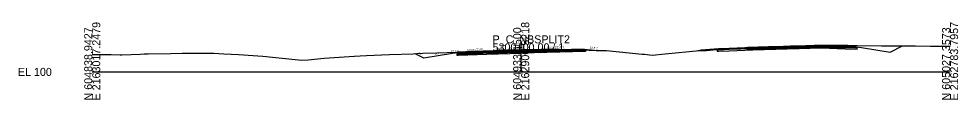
# Model space of a CAD drawing. Extents: x -26 to 1303, y -10 to 12038.
# Drawn here: x -25.7 to 302.8, y 10490.3 to 10517.3 of the extents above; entities that cross this region are included whole.
import ezdxf

# ---------------------------------------------------------------- set-up
doc = ezdxf.new("R2010")
doc.units = 0
for name, color, linetype in [('RD_GPK_XS_Cell', 7, 'Continuous'), ('RD_XS_Base', 7, 'Continuous'), ('RD_XS_ExGround', 7, 'Continuous'), ('RD_XS_ExPaveRet', 7, 'Continuous'), ('RD_XS_Greenside', 7, 'Continuous'), ('RD_XS_Pave', 7, 'Continuous'), ('RD_XS_PaveOvlay_CP', 7, 'Continuous'), ('RD_XS_TieSlope', 7, 'Continuous'), ('RD_XS_TX_Elev_EX', 7, 'Continuous'), ('RD_XS_TX_Elev_PR', 7, 'Continuous'), ('RD_XS_TX_ShdSlope', 7, 'Continuous'), ('RD_XS_TX_Slope', 7, 'Continuous')]:
    doc.layers.add(name, color=color, linetype=linetype)

msp = doc.modelspace()

# ---------------------------------------------------------------- linework, layer by layer
at = {"layer": 'RD_GPK_XS_Cell'}
for p, q in [((150, 10500), (150, 10510)), ((0, 10500), (150, 10500)), ((150, 10500), (300, 10500))]:
    msp.add_line(p, q, dxfattribs=at)
at = {"layer": 'RD_XS_Base'}
for p, q in [((138, 10506.72), (128, 10506.32)), ((150, 10507.04), (138, 10506.72)), ((138, 10506.72), (138, 10506.72)), ((138, 10506.22), (150, 10506.54)), ((150, 10507.04), (172.5, 10507.62)), ((150, 10506.54), (150, 10507.2)), ((150, 10507.2), (150, 10507.2)), ((150, 10507.2), (150, 10507.2)), ((150, 10507.2), (150, 10507.04)), ((172.5, 10507.12), (150, 10506.54)), ((150, 10507.04), (150, 10507.04)), ((150, 10506.54), (150, 10507.04)), ((150, 10507.04), (150, 10507.04)), ((150, 10507.04), (150, 10507.04)), ((150, 10506.54), (150, 10506.54)), ((172, 10507.61), (172, 10507.61)), ((172, 10507.61), (172, 10507.61)), ((172, 10507.61), (172, 10507.61)), ((172, 10507.11), (172, 10507.11)), ((172, 10507.11), (172, 10507.11)), ((172.5, 10507.62), (172.5, 10507.12)), ((172.5, 10507.59), (172.5, 10507.59)), ((218.68, 10507.74), (218.49, 10507.74)), ((218.49, 10507.74), (218.49, 10507.42)), ((218.49, 10507.42), (218.49, 10507.24)), ((218.49, 10507.24), (218.68, 10507.24)), ((218.99, 10507.76), (218.68, 10507.74)), ((218.68, 10507.24), (218.99, 10507.26)), ((222.72, 10507.91), (218.99, 10507.76)), ((218.99, 10507.26), (222.72, 10507.41)), ((231, 10508.24), (222.72, 10507.91)), ((222.72, 10507.41), (231, 10507.74)), ((243, 10508.57), (231, 10508.24)), ((231, 10507.74), (243, 10508.07)), ((243, 10508.63), (243, 10508.73)), ((243, 10508.73), (243, 10508.31)), ((247.18, 10508.69), (243, 10508.57)), ((243, 10508.57), (243, 10508.63)), ((243, 10508.57), (243, 10508.57)), ((243, 10508.57), (243, 10508.57)), ((243, 10508.25), (243, 10508.57)), ((243, 10508.31), (243, 10508.07)), ((243, 10508.07), (243, 10508.25)), ((243, 10508.07), (247.18, 10508.19)), ((255, 10508.91), (247.18, 10508.69)), ((247.18, 10508.19), (255, 10508.41)), ((262.93, 10508.59), (255, 10508.91)), ((255, 10508.41), (263.27, 10508.08)), ((267, 10508.43), (262.93, 10508.59)), ((263.27, 10508.08), (267.5, 10507.91)), ((267.33, 10508.42), (267, 10508.43)), ((267.5, 10508.41), (267.33, 10508.42)), ((267.5, 10508.08), (267.5, 10508.41)), ((267.5, 10507.91), (267.5, 10508.08)), ((128, 10506.32), (127.5, 10506.3)), ((127.5, 10506.3), (127.5, 10506.3)), ((127.5, 10506.3), (127.5, 10505.8)), ((127.5, 10505.8), (128, 10505.82)), ((128, 10506.32), (128, 10506.32)), ((128, 10505.82), (138, 10506.22)), ((128, 10505.82), (128, 10505.82)), ((138, 10506.22), (138, 10506.22))]:
    msp.add_line(p, q, dxfattribs=at)
at = {"layer": 'RD_XS_ExGround'}
msp.add_lwpolyline([(0, 10506.09), (1.12, 10506.08), (4.04, 10506.13), (6.56, 10506.04), (9.75, 10505.97), (10.38, 10505.93), (16.82, 10506.22), (18.16, 10506.32), (19.58, 10506.37), (27.53, 10506.4), (31.55, 10506.5), (33.93, 10506.5), (36.84, 10506.57), (42.56, 10506.59), (44.29, 10506.47), (46.05, 10506.38), (51.1, 10506.09), (59.64, 10505.5), (70.93, 10504.34), (73.32, 10504.07), (75.53, 10504.28), (81.08, 10504.79), (91.55, 10505.47), (91.7, 10505.48), (93.69, 10505.59), (95.88, 10505.76), (104, 10506.04), (112.27, 10506.32), (113.53, 10506.43), (115.57, 10506.58), (120.55, 10506.71), (127.66, 10506.87), (136.6, 10507.25), (140.47, 10507.41), (141.78, 10507.46), (145.18, 10507.57), (147.41, 10507.61), (147.56, 10507.66), (149.21, 10507.65), (149.28, 10507.64), (149.79, 10507.66), (150.63, 10507.68), (163.04, 10508.01), (171.28, 10507.74), (176.26, 10507.53), (179.14, 10507.5), (179.85, 10507.5), (192.28, 10506.22), (193.18, 10506.15), (195.82, 10505.88), (200.32, 10506.34), (212.39, 10507.46), (213.9, 10507.5), (214.82, 10507.5), (217.13, 10507.68), (229.11, 10508.51), (241.88, 10508.93), (244.23, 10508.98), (244.63, 10509.02), (249.27, 10509.16), (252.71, 10509.26), (263.2, 10509.25), (264.19, 10509.24), (267.45, 10509.19), (276.05, 10509.08), (280.35, 10509.1), (287.89, 10509.16), (293.1, 10509.05), (300, 10508.95)], dxfattribs=at)
at = {"layer": 'RD_XS_ExPaveRet'}
for points in [[(150.63, 10507.68), (149.79, 10507.66), (149.79, 10507.66), (149.28, 10507.64), (149.21, 10507.65), (149.21, 10507.65), (147.56, 10507.66), (147.56, 10507.66), (147.41, 10507.61), (147.41, 10507.61), (145.18, 10507.57), (145.18, 10507.57), (141.78, 10507.46), (141.78, 10507.46), (140.47, 10507.41), (136.6, 10507.25), (136.6, 10507.25), (127.66, 10506.87), (127.66, 10506.87), (127.66, 10506.87), (127.66, 10506.12), (127.66, 10506.12), (136.6, 10506.5), (136.6, 10506.5), (140.47, 10506.66), (141.78, 10506.71), (141.78, 10506.71), (145.18, 10506.82), (145.18, 10506.82), (147.41, 10506.86), (147.41, 10506.86), (147.56, 10506.91), (147.56, 10506.91), (149.21, 10506.9), (149.21, 10506.9), (149.28, 10506.89), (149.79, 10506.91), (149.79, 10506.91), (150.63, 10506.93), (150.63, 10506.93), (163.04, 10507.26), (163.04, 10508.01), (163.04, 10508.01), (150.63, 10507.68), (150.63, 10507.68)], [(150.63, 10507.68), (149.79, 10507.66), (149.28, 10507.64), (149.21, 10507.65), (147.56, 10507.66), (147.41, 10507.61), (145.18, 10507.57), (141.78, 10507.46), (140.47, 10507.41), (136.6, 10507.25), (127.66, 10506.87), (127.66, 10506.12), (136.6, 10506.5), (140.47, 10506.66), (141.78, 10506.71), (145.18, 10506.82), (147.41, 10506.86), (147.56, 10506.91), (149.21, 10506.9), (149.28, 10506.89), (149.79, 10506.91), (150.63, 10506.93), (163.04, 10507.26), (163.04, 10508.01), (150.63, 10507.68)], [(264.19, 10509.24), (264.19, 10509.24), (264.19, 10508.95), (264.19, 10508.49), (264.19, 10508.49), (264.19, 10508.49), (264.19, 10508.49), (263.2, 10508.5), (255.97, 10508.5), (252.71, 10508.51), (252.47, 10508.5), (249.52, 10508.41), (244.69, 10508.27), (244.63, 10508.27), (244.54, 10508.27), (244.13, 10508.22), (241.7, 10508.17), (236.55, 10508), (229.11, 10507.76), (229.11, 10508.27), (229.11, 10508.51), (236.55, 10508.75), (241.7, 10508.92), (244.13, 10508.97), (244.54, 10509.02), (244.63, 10509.02), (244.69, 10509.02), (249.52, 10509.16), (252.47, 10509.25), (252.71, 10509.26), (255.97, 10509.25), (263.2, 10509.25), (264.19, 10509.24), (264.19, 10509.24), (264.19, 10509.24)], [(264.19, 10509.24), (263.2, 10509.25), (255.97, 10509.25), (252.71, 10509.26), (252.47, 10509.25), (249.52, 10509.16), (244.69, 10509.02), (244.63, 10509.02), (244.54, 10509.02), (244.13, 10508.97), (241.7, 10508.92), (236.55, 10508.75), (229.11, 10508.51), (229.11, 10508.27), (229.11, 10507.76), (236.55, 10508), (241.7, 10508.17), (244.13, 10508.22), (244.54, 10508.27), (244.63, 10508.27), (244.69, 10508.27), (249.52, 10508.41), (252.47, 10508.5), (252.71, 10508.51), (255.97, 10508.5), (263.2, 10508.5), (264.19, 10508.49), (264.19, 10508.49), (264.19, 10508.95), (264.19, 10509.24), (264.19, 10509.24)]]:
    msp.add_lwpolyline(points, dxfattribs=at)
at = {"layer": 'RD_XS_Greenside'}
for p, q in [((126, 10506.48), (116, 10504.82)), ((212.99, 10507.59), (211.87, 10507.41)), ((269, 10508.59), (279, 10506.92)), ((279, 10506.92), (283.4, 10509.13)), ((116, 10504.82), (112.88, 10506.37))]:
    msp.add_line(p, q, dxfattribs=at)
at = {"layer": 'RD_XS_Pave'}
for p, q in [((138, 10507.04), (128, 10506.64)), ((128, 10506.48), (138, 10506.88)), ((138, 10506.88), (128, 10506.48)), ((128, 10506.32), (138, 10506.72)), ((128, 10506.64), (128, 10506.64)), ((128, 10506.64), (128, 10506.48)), ((128, 10506.48), (128, 10506.48)), ((128, 10506.48), (128, 10506.32)), ((150, 10507.35), (138, 10507.04)), ((138, 10506.88), (150, 10507.2)), ((150, 10507.2), (138, 10506.88)), ((138, 10507.04), (138, 10507.04)), ((138, 10506.72), (150, 10507.04)), ((138, 10506.88), (138, 10506.88)), ((138, 10506.88), (138, 10506.88)), ((138, 10506.72), (138, 10506.72)), ((172, 10507.93), (150, 10507.35)), ((172, 10507.77), (150, 10507.2)), ((150, 10507.2), (172, 10507.77)), ((150, 10507.04), (172, 10507.61)), ((150, 10507.35), (150, 10507.35)), ((150, 10507.2), (150, 10507.2)), ((150, 10507.2), (150, 10507.2)), ((150, 10507.2), (150, 10507.04)), ((150, 10507.2), (150, 10507.2)), ((150, 10507.04), (150, 10507.2)), ((150, 10507.2), (150, 10507.2)), ((150, 10507.2), (150, 10507.2)), ((150, 10507.04), (150, 10507.04)), ((150, 10507.04), (150, 10507.04)), ((172, 10507.77), (172, 10507.93)), ((172, 10507.93), (172, 10507.93)), ((172, 10507.93), (172, 10507.93)), ((172, 10507.93), (172, 10507.93)), ((172, 10507.61), (172, 10507.77)), ((172, 10507.77), (172, 10507.77)), ((172, 10507.77), (172, 10507.77)), ((172, 10507.77), (172, 10507.77)), ((172, 10507.77), (172, 10507.77)), ((172, 10507.77), (172, 10507.77)), ((172, 10507.61), (172, 10507.61)), ((172, 10507.61), (172, 10507.61)), ((222.72, 10508.22), (218.99, 10508.07)), ((218.99, 10508.07), (218.99, 10507.98)), ((222.72, 10508.06), (218.99, 10507.92)), ((218.99, 10507.92), (222.72, 10508.06)), ((218.99, 10507.98), (218.99, 10507.92)), ((218.99, 10507.92), (218.99, 10507.82)), ((218.99, 10507.76), (222.72, 10507.91)), ((218.99, 10507.82), (218.99, 10507.76)), ((231, 10508.56), (222.72, 10508.22)), ((231, 10508.4), (222.72, 10508.06)), ((222.72, 10508.06), (231, 10508.4)), ((222.72, 10507.91), (231, 10508.24)), ((243, 10508.89), (231, 10508.56)), ((243, 10508.73), (231, 10508.4)), ((231, 10508.4), (243, 10508.73)), ((231, 10508.24), (243, 10508.57)), ((247.18, 10509.01), (243, 10508.89)), ((247.18, 10508.85), (243, 10508.73)), ((243, 10508.73), (247.18, 10508.85)), ((243, 10508.63), (243, 10508.73)), ((243, 10508.73), (243, 10508.73)), ((243, 10508.73), (243, 10508.73)), ((243, 10508.73), (243, 10508.63)), ((243, 10508.57), (247.18, 10508.69)), ((243, 10508.57), (243, 10508.63)), ((243, 10508.63), (243, 10508.57)), ((243, 10508.57), (243, 10508.57)), ((243, 10508.57), (243, 10508.57)), ((255, 10509.23), (247.18, 10509.01)), ((255, 10509.07), (247.18, 10508.85)), ((247.18, 10508.85), (255, 10509.07)), ((247.18, 10508.69), (255, 10508.91)), ((262.93, 10508.91), (255, 10509.23)), ((262.93, 10508.75), (255, 10509.07)), ((255, 10509.07), (262.93, 10508.75)), ((255, 10508.91), (262.93, 10508.59)), ((267, 10508.75), (262.93, 10508.91)), ((267, 10508.59), (262.93, 10508.75)), ((262.93, 10508.75), (267, 10508.59)), ((262.93, 10508.59), (267, 10508.43)), ((267, 10508.64), (267, 10508.75)), ((267, 10508.59), (267, 10508.64)), ((267, 10508.48), (267, 10508.59)), ((267, 10508.43), (267, 10508.48))]:
    msp.add_line(p, q, dxfattribs=at)
at = {"layer": 'RD_XS_PaveOvlay_CP'}
for p, q in [((138, 10507.04), (128, 10506.64)), ((150, 10507.35), (138, 10507.04)), ((138, 10507.04), (138, 10507.04)), ((172, 10507.93), (150, 10507.35)), ((150, 10507.35), (150, 10507.35)), ((172, 10507.93), (172, 10507.93)), ((172, 10507.93), (172, 10507.93)), ((222.72, 10508.22), (218.99, 10508.07)), ((231, 10508.56), (222.72, 10508.22)), ((243, 10508.89), (231, 10508.56)), ((247.18, 10509.01), (243, 10508.89)), ((255, 10509.23), (247.18, 10509.01)), ((262.93, 10508.91), (255, 10509.23)), ((267, 10508.75), (262.93, 10508.91))]:
    msp.add_line(p, q, dxfattribs=at)
at = {"layer": 'RD_XS_TieSlope'}
for p, q in [((128, 10506.64), (126, 10506.48)), ((172, 10507.93), (176.95, 10507.52)), ((218.99, 10508.07), (212.99, 10507.59)), ((267, 10508.75), (269, 10508.59))]:
    msp.add_line(p, q, dxfattribs=at)

# ---------------------------------------------------------------- texts
at = {"layer": 'RD_GPK_XS_Cell'}
for s, p in [('E 2163017.2479', (2.8, 10490)), ('E 2162900.5218', (152.8, 10490)), ('E 2162783.7957', (302.8, 10490)), ('N 604838.9427', (0, 10490)), ('N 604933.1500', (150, 10490)), ('N 605027.3573', (300, 10490))]:
    msp.add_text(s, height=2.8, rotation=90, dxfattribs=at).set_placement(p)
for s, p in [('5300+00.00 / 1', (140, 10507.2)), ('P_C_NBSPLIT2', (140, 10510)), ('EL 100', (-26, 10498.6))]:
    msp.add_text(s, height=2.8, dxfattribs=at).set_placement(p)
at = {"layer": 'RD_XS_TX_Elev_EX'}
msp.add_text('107.67', height=0.6, rotation=90, dxfattribs=at).set_placement((149.74, 10508.15))
at = {"layer": 'RD_XS_TX_Elev_PR'}
msp.add_text('107.35', height=1, rotation=90, dxfattribs=at).set_placement((151.25, 10507.72))
at = {"layer": 'RD_XS_TX_ShdSlope'}
for rotation, p in [(4.5739, (125.37, 10506.72)), (355.4261, (173.89, 10508.13))]:
    msp.add_text('12.5:1', height=0.75, rotation=rotation, dxfattribs=at).set_placement(p)
at = {"layer": 'RD_XS_TX_Slope'}
for s, rotation, p in [('2:1', 333.4349, (113.75, 10506.44)), ('6:1', 9.4642, (119.89, 10505.91)), ('0.040 FT./FT.', 2.2906, (130.99, 10507.19)), ('0.028 FT./FT.', 1.6039, (141, 10507.56)), ('0.028 FT./FT.', 1.6039, (159, 10508.06))]:
    msp.add_text(s, height=0.75, rotation=rotation, dxfattribs=at).set_placement(p)

doc.saveas('drawing.dxf')
